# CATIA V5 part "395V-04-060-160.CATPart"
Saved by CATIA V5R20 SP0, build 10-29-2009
Part number: 395V-04-060-160
Source: Unknown
Property "A": "0.000"
Property "ARTICLENO": "395V-04-060-160"
Property "BOMINFO": "395V-04-060-160"
Property "CODE": "395V-04-060-160"
Property "D": "50.000"
Property "D1": "27.000"
Property "D2": "39.000"
Property "D3": "70.000"
Property "FORM": "A"
Property "L": "160.000"
Property "L1": "22.000"
Property "L2": "59.000"
Property "L3": "45.000"
Property "L4": "12.000"
Property "LINA": "395V-04-060-160"
Property "MAXLOAD": "5000 Kg"
Property "MDW": "10000 Kg"
Property "NB": "395V-04-060-160"
Property "NBSYN": "$CODE."
Property "NN": "395V"
Property "NT": "VDI 3366 Lifting Brackets"
Property "SUPPLIER": "CF"
Property "T": "25.500"
Property "W": "60.000"
Bounding box of the stored display mesh (mm): x -30 to 30, y 0 to 160, z -30 to 30
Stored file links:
  C:\Users\Utente\Desktop\3D files 395V\395V-04-060-160.CATPart
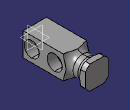
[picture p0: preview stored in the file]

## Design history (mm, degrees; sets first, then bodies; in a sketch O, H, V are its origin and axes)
Body1 "Geometry.1" (main body)
  Solid1 "395V-04-060-160.catpart": solid without history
